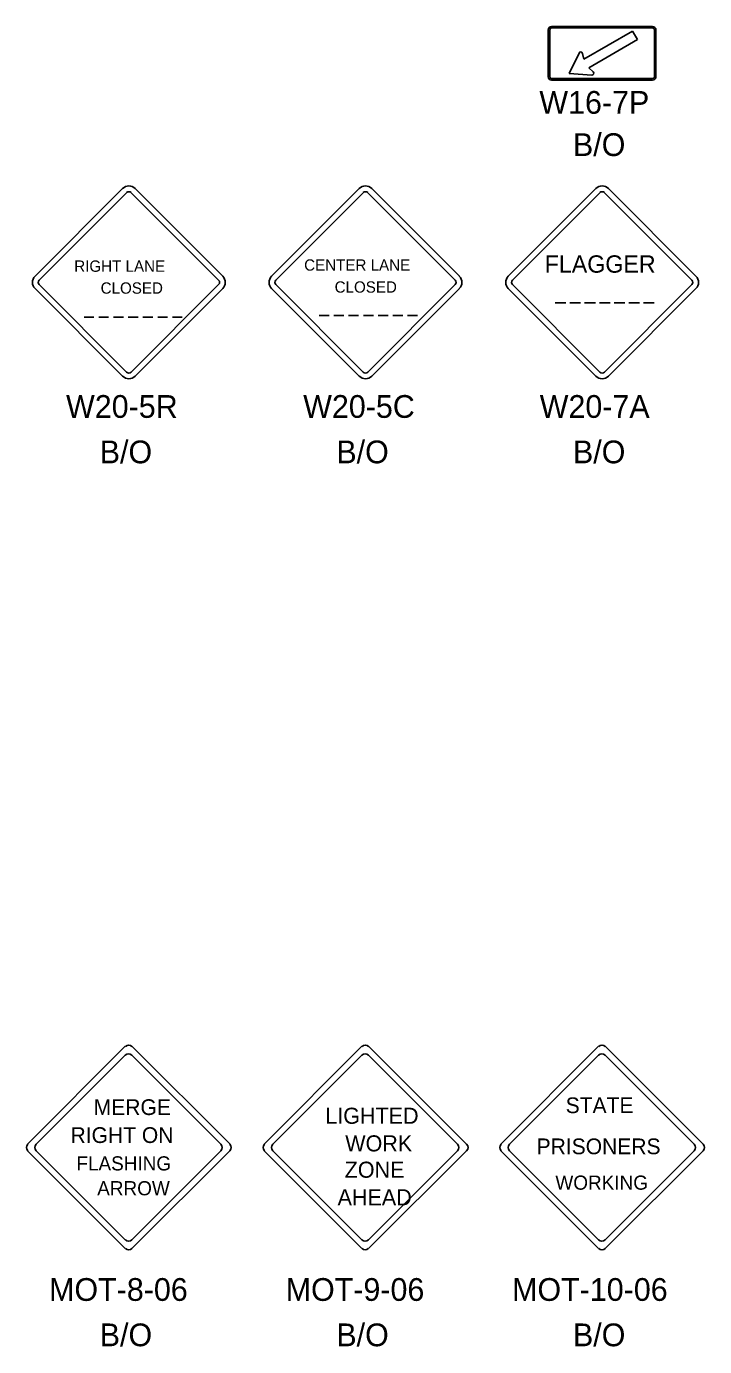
# Model space of a CAD drawing. Extents: x 10034 to 10794, y 10044 to 10499.
# Drawn here: x 10179 to 10283.3, y 10070.7 to 10273.8 of the extents above; entities that cross this region are included whole.
import ezdxf

# ---------------------------------------------------------------- set-up
doc = ezdxf.new("R2010")
doc.units = 0
for name, color, linetype in [('DSIndex', 7, 'Continuous'), ('DSSheetNo', 7, 'Continuous'), ('DSText', 7, 'Continuous'), ('DSTitle', 7, 'Continuous'), ('PlotBorder_dp', 7, 'Continuous')]:
    doc.layers.add(name, color=color, linetype=linetype)

msp = doc.modelspace()

# ---------------------------------------------------------------- linework, layer by layer
at = {"layer": 'DSIndex'}
for p, q in [((10264.76, 10268.78), (10272.24, 10273.1)), ((10272.24, 10273.1), (10273, 10271.8)), ((10273, 10271.8), (10265.51, 10267.48)), ((10262.51, 10266.61), (10264.01, 10269.74)), ((10264.55, 10269.68), (10264.76, 10268.78)), ((10265.97, 10266.34), (10262.51, 10266.61)), ((10265.51, 10267.48), (10266.19, 10266.84))]:
    msp.add_line(p, q, dxfattribs=at)
for points in [[(10259.29, 10266.08), (10259.29, 10273.32)], [(10259.52, 10266.08), (10259.52, 10273.32)], [(10259.8, 10273.84), (10275.33, 10273.84)], [(10259.8, 10273.6), (10275.33, 10273.6)], [(10275.61, 10273.32), (10275.61, 10266.08)], [(10275.85, 10273.32), (10275.85, 10266.08)], [(10275.33, 10265.8), (10259.8, 10265.8)], [(10275.33, 10265.56), (10259.8, 10265.56)]]:
    msp.add_lwpolyline(points, dxfattribs=at)
for centre, radius, start, end in [((10259.8, 10273.32), 0.518, 90, 180), ((10259.8, 10273.32), 0.28, 90, 180), ((10275.33, 10273.32), 0.518, 0, 90), ((10275.33, 10273.32), 0.28, 0, 90), ((10264.27, 10269.62), 0.288, 13.3557, 154.4881), ((10265.99, 10266.63), 0.288, 265.5119, 46.6443), ((10259.8, 10266.08), 0.518, 180, 270), ((10259.8, 10266.08), 0.28, 180, 270), ((10275.33, 10266.08), 0.518, 270, 360), ((10275.33, 10266.08), 0.28, 270, 360)]:
    msp.add_arc(centre, radius, start, end, dxfattribs=at)
at = {"layer": 'DSSheetNo'}
for p, q in [((10194.23, 10116.94), (10179.2, 10101.87)), ((10210.34, 10101.87), (10195.22, 10116.94)), ((10230.62, 10116.94), (10215.59, 10101.87)), ((10246.73, 10101.87), (10231.61, 10116.94)), ((10267.02, 10116.94), (10251.99, 10101.87)), ((10283.13, 10101.87), (10268.01, 10116.94)), ((10179.2, 10100.87), (10194.23, 10085.85)), ((10195.22, 10085.85), (10210.33, 10100.86)), ((10215.59, 10100.87), (10230.62, 10085.85)), ((10231.61, 10085.85), (10246.72, 10100.86)), ((10251.99, 10100.87), (10267.02, 10085.85)), ((10268.01, 10085.85), (10283.12, 10100.86))]:
    msp.add_line(p, q, dxfattribs=at)
for centre, start, end in [((10194.76, 10116.41), 45, 135), ((10231.15, 10116.41), 45, 135), ((10267.55, 10116.41), 45, 135), ((10179.73, 10101.38), 135, 225), ((10209.83, 10101.37), 315, 45), ((10216.12, 10101.38), 135, 225), ((10246.23, 10101.37), 315, 45), ((10252.52, 10101.38), 135, 225), ((10282.62, 10101.37), 315, 45), ((10194.76, 10086.34), 225, 315), ((10267.55, 10086.34), 225, 315)]:
    msp.add_arc(centre, 0.709, start, end, dxfattribs=at)
at = {"layer": 'DSText'}
for p, q in [((10180.35, 10235.42), (10193.82, 10248.89)), ((10195.74, 10248.89), (10209.21, 10235.42)), ((10216.74, 10235.41), (10230.22, 10248.89)), ((10232.13, 10248.89), (10245.61, 10235.41)), ((10253.13, 10235.41), (10266.61, 10248.89)), ((10268.53, 10248.89), (10282, 10235.41)), ((10193.82, 10220.02), (10180.35, 10233.5)), ((10193.82, 10220.02), (10180.35, 10233.5)), ((10209.21, 10233.5), (10195.74, 10220.02)), ((10209.21, 10233.5), (10195.74, 10220.02)), ((10230.22, 10220.02), (10216.74, 10233.5)), ((10245.61, 10233.5), (10232.13, 10220.02)), ((10266.61, 10220.02), (10253.13, 10233.5)), ((10282, 10233.5), (10268.53, 10220.02)), ((10260.35, 10231.33), (10262, 10231.33)), ((10262.62, 10231.33), (10264.26, 10231.33)), ((10264.88, 10231.33), (10266.53, 10231.33)), ((10267.15, 10231.33), (10268.79, 10231.33)), ((10269.41, 10231.33), (10271.06, 10231.33)), ((10271.68, 10231.33), (10273.32, 10231.33)), ((10273.94, 10231.33), (10275.58, 10231.33)), ((10187.88, 10229.11), (10189.41, 10229.11)), ((10190.15, 10229.11), (10191.67, 10229.11)), ((10192.41, 10229.11), (10193.94, 10229.11)), ((10194.68, 10229.11), (10196.2, 10229.11)), ((10196.94, 10229.11), (10198.47, 10229.11)), ((10199.21, 10229.11), (10200.73, 10229.11)), ((10201.47, 10229.11), (10203, 10229.11)), ((10224.06, 10229.37), (10225.58, 10229.37)), ((10226.32, 10229.37), (10227.85, 10229.37)), ((10228.58, 10229.37), (10230.11, 10229.37)), ((10230.85, 10229.37), (10232.38, 10229.37)), ((10233.11, 10229.37), (10234.64, 10229.37)), ((10235.38, 10229.37), (10236.91, 10229.37)), ((10237.64, 10229.37), (10239.17, 10229.37))]:
    msp.add_line(p, q, dxfattribs=at)
for centre, radius, start, end in [((10194.78, 10247.93), 1.36, 45, 135), ((10231.17, 10247.93), 1.36, 45, 135), ((10267.57, 10247.93), 1.36, 45, 135), ((10181.31, 10234.46), 1.36, 135, 225), ((10208.25, 10234.46), 1.36, 315, 45), ((10217.7, 10234.46), 1.36, 135, 225), ((10244.64, 10234.46), 1.36, 315, 45), ((10254.1, 10234.46), 1.36, 135, 225), ((10281.04, 10234.46), 1.36, 315, 45), ((10194.78, 10220.99), 1.36, 225, 315), ((10194.78, 10220.99), 1.36, 225, 315), ((10231.18, 10220.99), 1.36, 225, 315), ((10267.57, 10220.99), 1.36, 225, 315), ((10231.11, 10086.3), 0.663, 225, 315)]:
    msp.add_arc(centre, radius, start, end, dxfattribs=at)
at = {"layer": 'DSTitle'}
for p, q in [((10180.97, 10234.8), (10194.43, 10248.26)), ((10195.13, 10248.26), (10208.59, 10234.8)), ((10217.37, 10234.8), (10230.83, 10248.26)), ((10231.52, 10248.26), (10244.98, 10234.8)), ((10253.76, 10234.81), (10267.22, 10248.26)), ((10267.92, 10248.26), (10281.37, 10234.81)), ((10194.43, 10220.65), (10180.97, 10234.11)), ((10194.43, 10220.65), (10180.97, 10234.11)), ((10208.59, 10234.11), (10195.13, 10220.65)), ((10208.59, 10234.11), (10195.13, 10220.65)), ((10230.83, 10220.65), (10217.37, 10234.11)), ((10244.98, 10234.11), (10231.52, 10220.65)), ((10267.22, 10220.65), (10253.76, 10234.11)), ((10281.37, 10234.11), (10267.92, 10220.65)), ((10194.23, 10115.57), (10180.53, 10101.87)), ((10208.92, 10101.87), (10195.22, 10115.57)), ((10230.62, 10115.57), (10216.92, 10101.87)), ((10245.31, 10101.87), (10231.61, 10115.57)), ((10267.02, 10115.57), (10253.32, 10101.87)), ((10281.71, 10101.87), (10268.01, 10115.57)), ((10180.53, 10100.87), (10194.23, 10087.17)), ((10195.22, 10087.17), (10208.92, 10100.87)), ((10216.92, 10100.87), (10230.62, 10087.17)), ((10231.61, 10087.17), (10245.31, 10100.87)), ((10253.32, 10100.87), (10267.02, 10087.17)), ((10268.01, 10087.17), (10281.71, 10100.87))]:
    msp.add_line(p, q, dxfattribs=at)
for centre, radius, start, end in [((10194.78, 10247.92), 0.49, 45, 135), ((10231.17, 10247.92), 0.49, 45, 135), ((10267.57, 10247.92), 0.49, 45, 135), ((10181.32, 10234.46), 0.49, 135, 225), ((10208.24, 10234.46), 0.49, 315, 45), ((10217.71, 10234.46), 0.49, 135, 225), ((10244.63, 10234.46), 0.49, 315, 45), ((10254.11, 10234.46), 0.49, 135, 225), ((10281.03, 10234.46), 0.49, 315, 45), ((10194.78, 10221), 0.49, 225, 315), ((10194.78, 10221), 0.49, 225, 315), ((10231.17, 10221), 0.49, 225, 315), ((10267.57, 10221), 0.49, 225, 315), ((10194.72, 10115.06), 0.709, 45, 135), ((10231.11, 10115.06), 0.709, 45, 135), ((10267.51, 10115.06), 0.709, 45, 135), ((10181.04, 10101.38), 0.709, 135, 225), ((10217.43, 10101.38), 0.709, 135, 225), ((10253.83, 10101.38), 0.709, 135, 225), ((10208.42, 10101.38), 0.709, 315, 45), ((10244.81, 10101.38), 0.709, 315, 45), ((10281.21, 10101.38), 0.709, 315, 45), ((10194.74, 10087.67), 0.709, 225, 315), ((10231.12, 10087.67), 0.709, 225, 315), ((10267.52, 10087.67), 0.709, 225, 315)]:
    msp.add_arc(centre, radius, start, end, dxfattribs=at)

# ---------------------------------------------------------------- texts
at = {"layer": 'DSIndex'}
for s, p in [('W16-7P', (10257.91, 10260.4)), ('B/O', (10263.08, 10253.9))]:
    msp.add_text(s, height=3.5, dxfattribs=at).set_placement(p)
at = {"layer": 'PlotBorder_dp'}
for s, height, p in [('CENTER LANE', 1.7415, (10221.74, 10236.26)), ('FLAGGER', 2.67, (10258.73, 10235.95)), ('RIGHT LANE', 1.742, (10186.38, 10236.09)), ('CLOSED', 1.742, (10190.44, 10232.72)), ('CLOSED', 1.74, (10226.43, 10232.88)), ('W20-5R', 3.5, (10185.12, 10213.62)), ('W20-5C', 3.5, (10221.59, 10213.62)), ('W20-7A', 3.5, (10257.97, 10213.62)), ('B/O', 3.5, (10190.3, 10206.63)), ('B/O', 3.5, (10226.69, 10206.63)), ('B/O', 3.5, (10263.08, 10206.63)), ('MERGE', 2.42, (10189.37, 10106.37)), ('STATE', 2.42, (10261.96, 10106.66)), ('LIGHTED', 2.476, (10224.99, 10105.02)), ('RIGHT ON', 2.42, (10185.81, 10102.07)), ('WORK', 2.475, (10228.06, 10100.77)), ('PRISONERS', 2.42, (10257.49, 10100.34)), ('FLASHING', 2.178, (10186.71, 10097.84)), ('ZONE', 2.476, (10227.97, 10096.72)), ('ARROW', 2.178, (10189.91, 10094.02)), ('WORKING', 2.178, (10260.38, 10094.88)), ('AHEAD', 2.476, (10226.88, 10092.48)), ('MOT-8-06', 3.5, (10182.51, 10077.78)), ('MOT-9-06', 3.5, (10218.9, 10077.78)), ('MOT-10-06', 3.5, (10253.72, 10077.78)), ('B/O', 3.5, (10190.3, 10070.8)), ('B/O', 3.5, (10226.69, 10070.8)), ('B/O', 3.5, (10263.08, 10070.8))]:
    msp.add_text(s, height=height, dxfattribs=at).set_placement(p)

doc.saveas('drawing.dxf')
